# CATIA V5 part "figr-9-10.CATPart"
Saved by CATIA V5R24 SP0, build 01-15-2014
Part number: Part1
Bounding box of the stored display mesh (mm): x -15.705 to 98.193, y 0 to 272.268, z -20.723 to 20.723
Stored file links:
  D:\KAVITA\CATIA V5-6R2014 Project_ Kavita\CATIA V5-6R2014_partfiles\Partfiles\c09_catia_v5-6r2014_prt\figr-9-10.CATPart
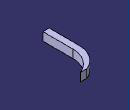
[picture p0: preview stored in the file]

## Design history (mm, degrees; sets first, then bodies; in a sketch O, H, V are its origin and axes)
Body1 (main body)
  Sketch1 on xy-plane, origin (0, 0, 0), H (1, 0, 0), V (0, 1, 0)
    line L1 (0, 0) -> (0, 150)
    arc A1 centre (131.8599, 150) radius 131.8599 from (0, 150) to (82.4884, 272.2681) cw
    length L1 = 150
    tangency: A1 L1
  Sketch2 on zx-plane, origin (0, 0, 0), H (-1, 0, 0), V (0, 0, 1)
    line L1 (15.7048, 20.7231) -> (15.7048, -20.7231)
    line L2 (15.7048, -20.7231) -> (-15.7048, -20.7231)
    line L3 (-15.7048, -20.7231) -> (-15.7048, 20.7231)
    line L4 (-15.7048, 20.7231) -> (15.7048, 20.7231)
    vertical: L1 V, L3 V
    horizontal: L2 H, L4 H
    equidistance: L1 L3 O, L2 L4 O
  Rib1: profile Sketch2, centre curve Sketch1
